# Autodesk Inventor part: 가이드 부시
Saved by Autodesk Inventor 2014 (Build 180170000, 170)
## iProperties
Created: 2026-06
Part Number: 가이드 부시
Material: 청동, 주조
Document SubType Name: Modeling
Designer: dg
Density: 8.87 g/cm^3
Appearance: 청동색 - 새틴
Mass: 78.5207 g
Surface Area: 46.814 cm^2
Volume: 8.85239 cm^3
Author: jhkim
Creation Date: 2026-05-29
Sending System: Autodesk Inventor 2027
Preprocessor: ST-DEVELOPER v20.1
Author: dg
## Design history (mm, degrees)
node "가이드 부시1"
node "솔리드1"
node "기준1"
